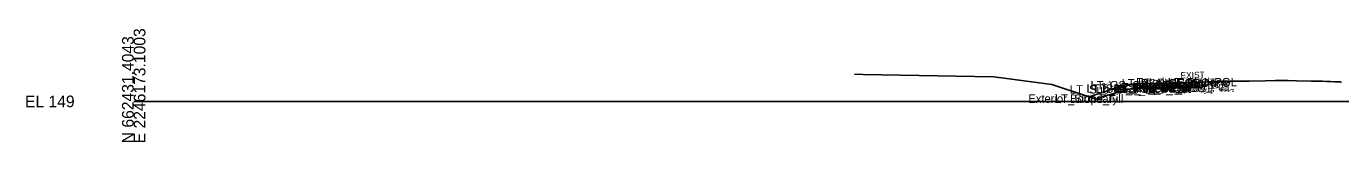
# Model space of a CAD drawing. Extents: x -26 to 603, y -10 to 9526.
# Drawn here: x -25.7 to 288.7, y 4990.3 to 5017.3 of the extents above; entities that cross this region are included whole.
import ezdxf

# ---------------------------------------------------------------- set-up
doc = ezdxf.new("R2010")
doc.units = 0
for name, color, linetype in [('Default', 7, 'Continuous'), ('Exist Cross Section Cell', 7, 'Continuous'), ('Exist XS Ground Line', 7, 'Continuous'), ('Prop CMT Pvmt Course 1', 7, 'Continuous'), ('Prop CMT Pvmt Course 2', 7, 'Continuous'), ('Prop CMT Pvmt Course 3', 7, 'Continuous'), ('Prop CMT Pvmt Surface', 7, 'Continuous'), ('Prop CMT Pvmt Surface Shoulder', 7, 'Continuous'), ('Prop CMT Shld Paved Course 1', 7, 'Continuous'), ('Prop CMT Shld Paved Course 2', 7, 'Continuous'), ('Prop CMT Shld Paved Course 3', 7, 'Continuous'), ('Prop CMT Slope Grass', 7, 'Continuous'), ('Prop CMT Subgrade Earthwork', 7, 'Continuous'), ('Prop XS SE Text', 7, 'Continuous'), ('Prop XS Side Slope Text', 7, 'Continuous'), ('Scratch_Level_2', 7, 'Continuous')]:
    doc.layers.add(name, color=color, linetype=linetype)

msp = doc.modelspace()

# ---------------------------------------------------------------- linework, layer by layer
at = {"layer": 'Exist Cross Section Cell'}
msp.add_line((0, 5000), (300, 5000), dxfattribs=at)
at = {"layer": 'Exist XS Ground Line'}
for p, q in [((172.39, 5006.55), (174.52, 5006.46)), ((174.52, 5006.46), (205.65, 5005.86)), ((205.65, 5005.86), (207.56, 5005.63)), ((207.56, 5005.63), (219.59, 5004.07)), ((219.59, 5004.07), (227.8, 5001.34)), ((233.29, 5001.61), (237.9, 5002.87)), ((237.9, 5002.87), (239.03, 5003.14)), ((239.03, 5003.14), (241.8, 5003.48)), ((241.8, 5003.48), (245.61, 5003.91)), ((245.61, 5003.91), (248.67, 5004.44)), ((248.67, 5004.44), (249.96, 5004.45)), ((249.96, 5004.45), (250.62, 5004.47)), ((250.62, 5004.47), (252.72, 5004.58)), ((252.72, 5004.58), (254.16, 5004.62)), ((254.16, 5004.62), (255.09, 5004.64)), ((255.09, 5004.64), (255.59, 5004.62)), ((255.59, 5004.62), (256.11, 5004.66)), ((256.11, 5004.66), (256.49, 5004.68)), ((256.49, 5004.68), (259.43, 5004.77)), ((259.43, 5004.77), (260.55, 5004.8)), ((260.55, 5004.8), (261.24, 5004.82)), ((261.24, 5004.82), (263.06, 5004.82)), ((263.06, 5004.82), (265.14, 5004.84)), ((265.14, 5004.84), (266.84, 5004.87)), ((266.84, 5004.87), (270.64, 5004.96)), ((270.64, 5004.96), (273.12, 5005)), ((273.12, 5005), (273.49, 5005.01)), ((273.49, 5005.01), (273.86, 5005)), ((273.86, 5005), (275.79, 5004.97)), ((275.79, 5004.97), (276.13, 5004.97)), ((276.13, 5004.97), (278.16, 5004.93)), ((278.16, 5004.93), (281.62, 5004.86)), ((281.62, 5004.86), (281.94, 5004.85)), ((281.94, 5004.85), (284.36, 5004.81)), ((284.36, 5004.81), (285.19, 5004.78)), ((285.19, 5004.78), (286.28, 5004.74)), ((286.28, 5004.74), (287.11, 5004.71)), ((287.11, 5004.71), (288.52, 5004.66)), ((288.52, 5004.66), (288.89, 5004.55)), ((227.8, 5001.34), (230.16, 5000.57)), ((230.16, 5000.57), (232.75, 5001.42)), ((232.75, 5001.42), (233.29, 5001.61))]:
    msp.add_line(p, q, dxfattribs=at)
at = {"layer": 'Prop CMT Pvmt Course 1'}
for points in [[(255.59, 5004.62), (249.5, 5004.47)], [(249.5, 5004.47), (249.5, 5003.55)], [(249.5, 5003.55), (255.59, 5003.7)], [(255.59, 5003.7), (255.59, 5004.62)]]:
    msp.add_lwpolyline(points, dxfattribs=at)
at = {"layer": 'Prop CMT Pvmt Course 2'}
for points in [[(255.59, 5003.7), (249.5, 5003.55)], [(249.5, 5003.55), (249.5, 5003.22)], [(249.5, 5003.22), (255.59, 5003.37)], [(255.59, 5003.37), (255.59, 5003.7)]]:
    msp.add_lwpolyline(points, dxfattribs=at)
at = {"layer": 'Prop CMT Pvmt Course 3'}
for points in [[(255.59, 5003.37), (249.5, 5003.22)], [(249.5, 5003.22), (255.59, 5003.37)], [(249.5, 5003.22), (249.5, 5003.22)], [(255.59, 5003.37), (255.59, 5003.37)]]:
    msp.add_lwpolyline(points, dxfattribs=at)
at = {"layer": 'Prop CMT Pvmt Surface'}
msp.add_lwpolyline([(255.59, 5004.62), (249.5, 5004.47)], dxfattribs=at)
at = {"layer": 'Prop CMT Pvmt Surface Shoulder'}
msp.add_lwpolyline([(249.5, 5004.47), (239.96, 5004.23)], dxfattribs=at)
at = {"layer": 'Prop CMT Shld Paved Course 1'}
for p, q in [((239.96, 5004.23), (239.02, 5003.29)), ((249.5, 5004.47), (245.5, 5004.37))]:
    msp.add_line(p, q, dxfattribs=at)
for points in [[(244.56, 5003.43), (249.5, 5003.55)], [(249.5, 5003.55), (249.5, 5004.47)]]:
    msp.add_lwpolyline(points, dxfattribs=at)
at = {"layer": 'Prop CMT Shld Paved Course 2'}
for p, q in [((239.02, 5003.29), (238.68, 5002.95)), ((249.5, 5003.55), (239.02, 5003.29))]:
    msp.add_line(p, q, dxfattribs=at)
for points in [[(244.22, 5003.09), (249.5, 5003.22)], [(249.5, 5003.22), (249.5, 5003.55)]]:
    msp.add_lwpolyline(points, dxfattribs=at)
at = {"layer": 'Prop CMT Shld Paved Course 3'}
for points in [[(249.5, 5003.22), (244.22, 5003.09), (243.72, 5003.07)], [(243.72, 5003.07), (249.5, 5003.22)], [(243.72, 5003.07), (243.72, 5003.07)], [(249.5, 5003.22), (249.5, 5003.22)]]:
    msp.add_lwpolyline(points, dxfattribs=at)
at = {"layer": 'Prop CMT Slope Grass'}
for p, q in [((237.34, 5004.02), (228.55, 5001.09)), ((239.96, 5004.23), (239.5, 5004.19))]:
    msp.add_line(p, q, dxfattribs=at)
msp.add_lwpolyline([(239.5, 5004.19), (237.34, 5004.02)], dxfattribs=at)
at = {"layer": 'Prop CMT Subgrade Earthwork'}
for points in [[(243.72, 5003.07), (233.76, 5002.83)], [(249.5, 5003.22), (243.72, 5003.07)], [(255.59, 5003.37), (249.5, 5003.22)]]:
    msp.add_lwpolyline(points, dxfattribs=at)

# ---------------------------------------------------------------- texts
at = {"layer": 'Default'}
msp.add_text('-', height=0.0001, dxfattribs=at).set_placement((0, 5000))
msp.add_text('-', height=0.0001, dxfattribs=at).set_placement((0, 5000))
msp.add_text('-', height=0.0001, dxfattribs=at).set_placement((0, 5000))
msp.add_text('-', height=0.0001, dxfattribs=at).set_placement((0, 5000))
at = {"layer": 'Exist Cross Section Cell'}
for s, p in [('N 662431.4043', (0, 4990)), ('E 2246173.1003', (2.8, 4990))]:
    msp.add_text(s, height=2.8, rotation=90, dxfattribs=at).set_placement(p)
msp.add_text('EL 149', height=2.8, dxfattribs=at).set_placement((-26, 4998.6))
at = {"layer": 'Prop XS SE Text'}
msp.add_text('EXIST', height=1.5, rotation=1.4321, dxfattribs=at).set_placement((250.4, 5005.49))
at = {"layer": 'Prop XS Side Slope Text'}
msp.add_text('3:1', height=1.5, rotation=18.4332, dxfattribs=at).set_placement((231.81, 5002.74))
at = {"layer": 'Scratch_Level_2'}
for s, p in [('LT_PS1_OEOP', (236.3, 5003.37)), ('Exterior Boundary', (239.73, 5003.62)), ('LT_PV1_OEOT', (240.24, 5003.47)), ('LT_PV1_PGL', (247.37, 5003.62)), ('LT_Sub_OSS_DLT', (223.92, 5001.89)), ('LT_Sub_Trench_Out', (227.92, 5002.07)), ('LT_GS_OS_CTL', (228.87, 5002.89)), ('LT_PS3_Shelf_Out', (229.7, 5002.07)), ('LT_PS3_OEOP', (234.46, 5002.09)), ('LT_PS2_OEOP', (234.8, 5002.43)), ('LT_Sub_OEOT', (239.58, 5002.22)), ('LT_PV2_OEOT', (239.67, 5002.55)), ('LT_PV3_OEOT', (239.67, 5002.22)), ('LT_Sub_PGL', (246.7, 5002.37)), ('LT_PV2_PGL', (246.8, 5002.7)), ('LT_PV3_PGL', (246.8, 5002.37)), ('Exterior Boundary', (213.99, 4999.67)), ('LT_Slope_Fill', (220.37, 4999.67))]:
    msp.add_text(s, height=2, dxfattribs=at).set_placement(p)

doc.saveas('drawing.dxf')
